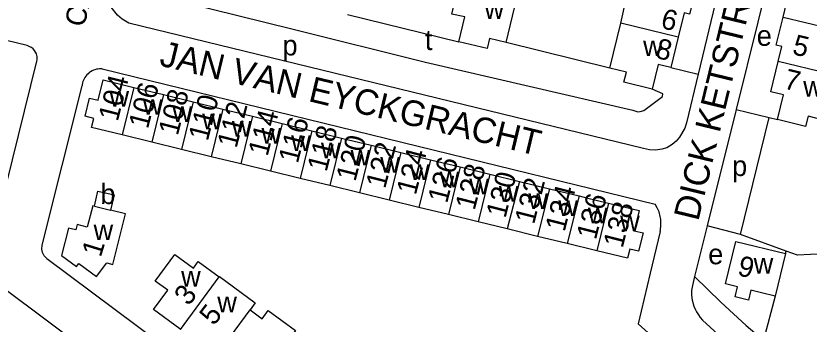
# Model space of a CAD drawing. Extents: x 162804 to 165059, y 381530 to 382901.
# Drawn here: x 163853.2 to 164009, y 382108.7 to 382169.2 of the extents above; entities that cross this region are included whole.
import ezdxf

# ---------------------------------------------------------------- set-up
doc = ezdxf.new("R2010")
doc.units = 0
for name, color, linetype in [('BLT_Basislijn', 7, 'Continuous'), ('BLT_Bebouwing', 7, 'Continuous'), ('BLT_Centroide', 7, 'Continuous'), ('BLT_Huisnummer', 7, 'Continuous'), ('BLT_Huisnummer_ tussenligend', 7, 'Continuous'), ('BLT_Onderverdeling_panden', 7, 'Continuous'), ('BLT_Straatnaam', 7, 'Continuous'), ('BLT_Straatnaam_verkleind', 7, 'Continuous')]:
    doc.layers.add(name, color=color, linetype=linetype)

msp = doc.modelspace()

# ---------------------------------------------------------------- linework, layer by layer
at = {"layer": 'BLT_Basislijn'}
for p, q in [((163918.39, 382169.46), (163940.23, 382164.12)), ((163969.89, 382158.98), (163949.56, 382164.01)), ((163981.87, 382159.09), (163987.24, 382157.76)), ((163870.19, 382158.8), (163978.82, 382132.25)), ((163994.7, 382150.85), (164001.17, 382149.25)), ((164001.17, 382149.25), (164002.84, 382148.85)), ((163989.03, 382128), (163986.54, 382118.01)), ((163995.59, 382126.3), (163989.03, 382128)), ((163979.76, 382126.89), (163977.83, 382118.69)), ((164004.52, 382123.02), (163995.59, 382126.3)), ((164004.41, 382122.54), (164004.52, 382123.02)), ((163977.83, 382118.69), (163975.44, 382108.72)), ((164002.37, 382114.16), (164000.11, 382105.51))]:
    msp.add_line(p, q, dxfattribs=at)
for points in [[(163990.58, 382190.16), (163993.12, 382189.56), (163993.32, 382189.5), (163993.66, 382189.33), (163993.97, 382189.06), (163994.08, 382188.94), (163994.23, 382188.71), (163994.35, 382188.48), (163994.41, 382188.27), (163994.45, 382187.99), (163994.45, 382187.71), (163994.41, 382187.5), (163987.24, 382157.76)], [(164008.03, 382185.9), (164005.26, 382186.5), (164004.88, 382186.53), (164004.54, 382186.49), (164004.34, 382186.43), (164004.11, 382186.34), (164003.96, 382186.25), (164003.83, 382186.15), (164003.72, 382186.05), (164003.62, 382185.94), (164003.51, 382185.82), (164003.38, 382185.61), (164003.32, 382185.5), (164003.22, 382185.21), (163994.7, 382150.85)], [(163987.24, 382157.76), (163984.94, 382148.24), (163984.64, 382147.18), (163983.6, 382145.36), (163982.94, 382144.58), (163982.16, 382143.92), (163981.12, 382143.31), (163980.14, 382143.01), (163978.95, 382142.83), (163977.69, 382142.88), (163976.49, 382143.14), (163875.45, 382167.79), (163874.13, 382168.56), (163873.22, 382169.37), (163871.97, 382170.95), (163871.4, 382172.12), (163871.12, 382173.15), (163870.96, 382174.4), (163871.1, 382175.35), (163873.59, 382185.49)], [(163850.17, 382131.14), (163857.34, 382160.32), (163857.4, 382160.6), (163857.41, 382161.06), (163857.4, 382161.22), (163857.28, 382161.74), (163857.13, 382162.09), (163856.93, 382162.41), (163856.65, 382162.72), (163856.32, 382162.98), (163856.12, 382163.1), (163855.71, 382163.29), (163855.49, 382163.37), (163793.44, 382178.49), (163792.98, 382178.52), (163792.81, 382178.51), (163792.52, 382178.45), (163792.24, 382178.33), (163792.02, 382178.19), (163791.8, 382177.98), (163791.69, 382177.84), (163791.52, 382177.59), (163791.39, 382177.2)], [(163880.42, 382178.71), (163879.15, 382178.67), (163878.78, 382174.2), (163881.18, 382173.21), (163907.43, 382166.66), (163933.68, 382160.11), (163954.04, 382155.4), (163974.39, 382150.68), (163975.42, 382150.4), (163975.89, 382150.46), (163976.55, 382150.6), (163980.27, 382153.38), (163980.3, 382153.9), (163978.21, 382154.83)], [(163870.19, 382158.8), (163869.92, 382158.82), (163869.64, 382158.81), (163869.35, 382158.78), (163869.06, 382158.73), (163868.77, 382158.64), (163868.48, 382158.54), (163868.2, 382158.41), (163867.92, 382158.25), (163867.66, 382158.07), (163867.42, 382157.86), (163867.2, 382157.64), (163867, 382157.4), (163866.82, 382157.14), (163866.66, 382156.88), (163866.53, 382156.6), (163866.43, 382156.33), (163866.35, 382156.05), (163866.3, 382155.77), (163866.26, 382155.5)], [(163859.34, 382121.57), (163858.83, 382122.05), (163858.47, 382122.73), (163858.33, 382123.39), (163858.43, 382124.17), (163866.26, 382155.5)], [(163994.7, 382150.85), (163989.03, 382128)], [(163995.59, 382126.3), (164001.17, 382149.25)], [(164039.67, 382139.88), (164037.84, 382131.18), (164027.49, 382130.14), (164018.69, 382126.06), (164011.89, 382122.47), (164006.76, 382122.19), (164004.52, 382123.02)], [(163979.76, 382126.89), (163979.82, 382127.18), (163979.87, 382127.46), (163979.91, 382127.75), (163979.93, 382128.05), (163979.94, 382128.34), (163979.94, 382128.64), (163979.93, 382128.94), (163979.9, 382129.24), (163979.86, 382129.54), (163979.8, 382129.83), (163979.74, 382130.12), (163979.66, 382130.41), (163979.56, 382130.7), (163979.46, 382130.98), (163979.34, 382131.25), (163979.21, 382131.51), (163978.82, 382132.25)], [(163915.4, 382046.58), (163929.16, 382041.32), (163929.98, 382041.14), (163930.83, 382041.26), (163931.5, 382041.58), (163931.96, 382041.99), (163932.39, 382042.66), (163935.5, 382049.87), (163935.74, 382050.87), (163935.68, 382051.49), (163935.36, 382052.23), (163934.83, 382052.85), (163850.87, 382115.63), (163850.01, 382116.38), (163849.32, 382117.21), (163848.78, 382118.13), (163848.37, 382119.03), (163848.07, 382120.09), (163847.96, 382120.7), (163847.96, 382121.67)], [(163859.34, 382121.57), (163925.88, 382071.87)], [(163986.54, 382118.01), (163986.11, 382116.26), (163985.96, 382115.24), (163985.96, 382114.35), (163986.09, 382113.39), (163986.43, 382112.19), (163986.73, 382111.49), (163986.92, 382111.1), (163987.32, 382110.47), (163987.66, 382109.97), (163988.09, 382109.47), (163993.41, 382104.62), (164000.55, 382098.6), (164009.36, 382091.88)], [(163986.54, 382118.01), (163991.7, 382112.95), (163996.71, 382108.38), (164000.11, 382105.51)], [(163975.44, 382108.72), (163990.12, 382095.52), (164004.84, 382084.13)]]:
    msp.add_lwpolyline(points, dxfattribs=at)
at = {"layer": 'BLT_Bebouwing'}
for p, q in [((163972.04, 382167.78), (163973.93, 382176.28)), ((164003.94, 382168.99), (164006.01, 382177.44)), ((163969.89, 382158.98), (163972.04, 382167.78)), ((163870.41, 382156.64), (163876.41, 382155.18)), ((163876.41, 382155.18), (163882.23, 382153.76)), ((163882.23, 382153.76), (163888.07, 382152.33)), ((163888.07, 382152.33), (163893.88, 382150.91)), ((163893.88, 382150.91), (163899.72, 382149.49)), ((163899.72, 382149.49), (163905.56, 382148.07)), ((163874.13, 382145.82), (163868.13, 382147.28)), ((163905.56, 382148.07), (163911.39, 382146.64)), ((163911.39, 382146.64), (163917.22, 382145.22)), ((163879.95, 382144.4), (163874.13, 382145.82)), ((163917.22, 382145.22), (163923.05, 382143.8)), ((163885.77, 382142.98), (163879.95, 382144.4)), ((163923.05, 382143.8), (163928.88, 382142.38)), ((163891.59, 382141.55), (163885.77, 382142.98)), ((163928.88, 382142.38), (163934.71, 382140.96)), ((163897.42, 382140.13), (163891.59, 382141.55)), ((163934.71, 382140.96), (163940.52, 382139.54)), ((163903.24, 382138.71), (163897.42, 382140.13)), ((163940.52, 382139.54), (163946.35, 382138.12)), ((163909.08, 382137.28), (163903.24, 382138.71)), ((163914.89, 382135.87), (163909.09, 382137.28)), ((163946.35, 382138.11), (163952.16, 382136.7)), ((163920.74, 382134.44), (163914.89, 382135.87)), ((163952.16, 382136.7), (163958.02, 382135.27)), ((163926.56, 382133.02), (163920.74, 382134.44)), ((163958.02, 382135.27), (163963.85, 382133.85)), ((163932.41, 382131.59), (163926.56, 382133.02)), ((163963.85, 382133.85), (163965.31, 382133.49)), ((163965.31, 382133.49), (163969.67, 382132.43)), ((163868.38, 382131.89), (163867.27, 382127.7)), ((163868.66, 382131.85), (163868.38, 382131.89)), ((163874.78, 382130.33), (163871.82, 382131.06)), ((163938.23, 382130.17), (163932.41, 382131.59)), ((163969.67, 382132.43), (163975.67, 382130.97)), ((163872.32, 382120.37), (163874.78, 382130.33)), ((163944.07, 382128.75), (163938.23, 382130.17)), ((163949.77, 382127.35), (163944.07, 382128.75)), ((163955.71, 382125.9), (163949.77, 382127.36)), ((163961.53, 382124.48), (163955.71, 382125.9)), ((163967.38, 382123.05), (163961.53, 382124.48)), ((163973.39, 382121.63), (163967.38, 382123.05)), ((164004.41, 382122.54), (164002.37, 382114.16)), ((163869.1, 382117.99), (163871.09, 382120.68)), ((163871.09, 382120.68), (163872.32, 382120.37)), ((163880.28, 382111.53), (163883.07, 382115.32))]:
    msp.add_line(p, q, dxfattribs=at)
for points in [[(163940.23, 382164.12), (163941.44, 382169.02), (163938.87, 382169.58), (163940.33, 382175.55)], [(163986.45, 382173.25), (163985.56, 382169.54), (163984.48, 382169.81), (163983.33, 382165.06)], [(163949.56, 382164.01), (163951.65, 382172.77)], [(164002.95, 382160.28), (164003.66, 382163.19), (164002.58, 382163.44), (164003.94, 382168.99)], [(163949.56, 382164.01), (163946.3, 382164.79), (163945.82, 382162.79), (163940.23, 382164.12)], [(163983.33, 382165.06), (163981.87, 382159.09)], [(163981.87, 382159.09), (163979.38, 382159.69), (163978.21, 382154.83)], [(164002.84, 382148.85), (164004.01, 382153.7), (164001.5, 382154.32), (164002.95, 382160.28)], [(163978.21, 382154.83), (163972.68, 382156.18), (163973.17, 382158.18), (163969.89, 382158.98)], [(163868.13, 382147.28), (163868.56, 382149.07), (163866.83, 382149.49), (163867.71, 382153.07), (163869.44, 382152.66), (163870.41, 382156.64)], [(164012.11, 382148.69), (164008.84, 382149.49), (164008.35, 382147.5), (164002.84, 382148.85)], [(163868.66, 382131.85), (163869.33, 382134.78), (163872.56, 382134.03), (163871.82, 382131.06)], [(163975.67, 382130.97), (163974.71, 382127.01), (163976.43, 382126.59), (163975.54, 382122.99), (163973.82, 382123.42), (163973.39, 382121.63)], [(163867.27, 382127.7), (163865.31, 382128.21), (163865.03, 382127.16), (163863.56, 382127.54), (163862.24, 382122.13)], [(164002.37, 382114.16), (163999.71, 382114.83), (163997.61, 382115.32), (163997.13, 382113.38), (163994.52, 382114.03), (163995, 382115.96), (163992.62, 382116.56), (163994.66, 382124.92), (164004.41, 382122.54)], [(163862.24, 382122.13), (163865.17, 382119.96), (163865.61, 382120.56), (163869.1, 382117.99)], [(163883.07, 382115.32), (163880.62, 382117.11), (163884.47, 382122.34)], [(163884.47, 382122.34), (163888.12, 382119.65), (163889.08, 382120.95), (163893.17, 382117.94)], [(163893.17, 382117.94), (163893.24, 382118.03)], [(163893.24, 382118.03), (163900.25, 382112.86), (163899.24, 382111.48)], [(163885.44, 382107.71), (163880.28, 382111.53)], [(163899.24, 382111.48), (163901.64, 382109.72), (163902.82, 382111.33), (163908.14, 382107.42), (163905.48, 382103.8)]]:
    msp.add_lwpolyline(points, dxfattribs=at)
at = {"layer": 'BLT_Onderverdeling_panden'}
for p, q in [((164003.94, 382168.99), (164016.47, 382165.91)), ((163983.33, 382165.06), (163972.04, 382167.78)), ((164014.26, 382157.5), (164002.95, 382160.28)), ((163876.41, 382155.18), (163874.13, 382145.82)), ((163882.23, 382153.76), (163879.95, 382144.4)), ((163888.07, 382152.33), (163885.77, 382142.98)), ((163893.88, 382150.91), (163891.59, 382141.55)), ((163899.72, 382149.49), (163897.42, 382140.13)), ((163905.56, 382148.07), (163903.24, 382138.71)), ((163911.39, 382146.64), (163909.09, 382137.28)), ((163917.22, 382145.22), (163914.89, 382135.87)), ((163923.05, 382143.8), (163920.74, 382134.44)), ((163928.88, 382142.38), (163926.56, 382133.02)), ((163934.71, 382140.96), (163932.41, 382131.59)), ((163940.52, 382139.54), (163938.23, 382130.17)), ((163946.35, 382138.11), (163944.07, 382128.75)), ((163952.16, 382136.7), (163949.77, 382127.36)), ((163958.02, 382135.27), (163955.71, 382125.9)), ((163963.85, 382133.85), (163961.53, 382124.48)), ((163868.66, 382131.85), (163871.82, 382131.06)), ((163969.67, 382132.43), (163967.38, 382123.05)), ((163895.39, 382106.24), (163899.24, 382111.48))]:
    msp.add_line(p, q, dxfattribs=at)
msp.add_lwpolyline([(163885.44, 382107.71), (163885.56, 382107.62), (163893.17, 382117.94)], dxfattribs=at)

# ---------------------------------------------------------------- texts
at = {"layer": 'BLT_Centroide'}
for s, p in [('w', (163945.27, 382168.62)), ('t', (163933.59, 382162.51)), ('e', (163998.75, 382163.34)), ('p', (163905.6, 382161.44)), ('w', (163976.43, 382161.31)), ('w', (164007.88, 382153.34)), ('w', (163871.62, 382151.39)), ('w', (163878.19, 382149.78)), ('w', (163884, 382148.36)), ('w', (163889.83, 382146.95)), ('w', (163895.66, 382145.52)), ('w', (163901.48, 382144.09)), ('w', (163907.31, 382142.67)), ('w', (163913.16, 382141.25)), ('w', (163918.97, 382139.83)), ('w', (163924.81, 382138.41)), ('p', (163993.91, 382137.75)), ('w', (163930.62, 382136.98)), ('w', (163936.47, 382135.56)), ('b', (163869.84, 382132.24)), ('w', (163942.3, 382134.14)), ('w', (163948.11, 382132.72)), ('w', (163953.89, 382131.31)), ('w', (163959.78, 382129.88)), ('w', (163965.59, 382128.45)), ('w', (163971.91, 382126.92)), ('w', (163868.5, 382125.16)), ('e', (163989.22, 382120.42)), ('w', (163998.14, 382118.58)), ('w', (163885.69, 382116.05)), ('w', (163892.8, 382111))]:
    msp.add_text(s, height=4, dxfattribs=at).set_placement(p)
at = {"layer": 'BLT_Huisnummer'}
for s, rotation, p in [('8', 346.4888, (163978.65, 382161.03)), ('7', 346.4888, (164003.87, 382155)), ('104', 75.6316, (163873.25, 382148.33)), ('108', 75.6316, (163885.04, 382145.55)), ('112', 75.6316, (163896.58, 382143.08)), ('116', 75.6316, (163908.61, 382140.08)), ('120', 75.6316, (163919.92, 382136.53)), ('124', 75.6316, (163931.79, 382133.86)), ('128', 75.6316, (163943.34, 382130.88)), ('132', 75.6316, (163955.01, 382128.13)), ('138', 75.6316, (163972.4, 382123.44)), ('1', 72.9218, (163869.91, 382121.65)), ('9', 346.2948, (163994.78, 382118.32)), ('3', 52.6016, (163887.19, 382112.09))]:
    msp.add_text(s, height=4, rotation=rotation, dxfattribs=at).set_placement(p)
at = {"layer": 'BLT_Huisnummer_ tussenligend'}
for s, rotation, p in [('6', 345.7737, (163979.7, 382166.89)), ('5', 346.4888, (164005.56, 382161.74)), ('106', 75.6316, (163879.18, 382146.87)), ('110', 75.6316, (163890.93, 382144.48)), ('114', 75.6316, (163902.67, 382141.49)), ('118', 75.6316, (163914.26, 382138.43)), ('122', 75.6316, (163925.77, 382135.13)), ('126', 75.6316, (163937.93, 382132.24)), ('130', 75.6316, (163949.39, 382129.33)), ('134', 75.6316, (163961.01, 382126.66)), ('136', 75.6316, (163967.15, 382125.08)), ('5', 52.5963, (163892.14, 382108.19))]:
    msp.add_text(s, height=4, rotation=rotation, dxfattribs=at).set_placement(p)
at = {"layer": 'BLT_Straatnaam'}
for s, height, rotation, p in [('DICK KETSTRAAT', 5, 76.4061, (163987.26, 382128.74)), ('JAN VAN EYCKGRACHT', 4.9999, 346.5464, (163881.24, 382159.51))]:
    msp.add_text(s, height=height, rotation=rotation, dxfattribs=at).set_placement(p)
at = {"layer": 'BLT_Straatnaam_verkleind'}
msp.add_text('CAREL WILLINKSTRAAT', height=4, rotation=75.7614, dxfattribs=at).set_placement((163866.62, 382166.83))

doc.saveas('drawing.dxf')
